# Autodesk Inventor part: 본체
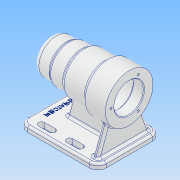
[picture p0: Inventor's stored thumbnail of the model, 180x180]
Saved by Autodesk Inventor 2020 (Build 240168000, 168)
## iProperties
Created: 2021-10
Part Number: 본체
Material: 알루미늄 6061
Document SubType Name: Modeling
Designer: user
Density: 2.7 g/cm^3
Appearance: 알루미늄 - 평지
Mass: 691.044 g
Surface Area: 699.056 cm^2
Volume: 255.942 cm^3
Author: user
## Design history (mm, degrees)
sketch "스케치1"
  geometry: L1 (56, 0)-(-56, 0); L2 (-56, 0)-(-56, 25); L3 (-56, 25)-(-32, 25); L4 (-32, 25)-(-32, 27); L5 (-32, 27)-(-10, 27); L6 (-10, 27)-(-10, 30); L7 (-10, 30)-(24, 30); L8 (24, 30)-(24, 34); L9 (24, 34)-(56, 34); L10 (56, 34)-(56, 0); 1 further point
  constraints: 20 end point, 7 perpendicular, 1 horizontal, 1 vertical
  dimensions: "d0" = 112 distance of L1.start L1.end; "d1" = 25 distance of L1.end L2.end; "d2" = 24 distance of L2.end L3.end; "d3" = 2 distance of L3.end L4.end; "d5" = 3 distance of L5.end L6.end; "d6" = 34 distance of L6.end L7.end; "d7" = 4 distance of L7.end L8.end; "d8" = 32 distance of L8.end L9.end; "d9" = 56 distance from line of point (0, 0) L2; "d10" = 34 distance from line of point (0, 0) L9; "d89" = 46 distance between parallel lines of L2 L6
revolve "회전1" sketch "스케치1" stored, may be unused: angle "d11" = 90 deg
node "작업 평면1"
sketch "스케치2"
  geometry: L1 (56, -45)-(-56, -45); L2 (-56, -45)-(-56, 45); L3 (-56, 45)-(56, 45); L4 (56, 45)-(56, -45); L5 (56, -45)-(-56, 45); L6 (-56, -45)-(56, 45); 1 further point
  constraints: 12 end point, 2 midpoint, 2 parallel, 1 horizontal, 1 perpendicular
  dimensions: "d13" = 112 distance of L1.start L1.end; "d14" = 90 distance of L1.end L2.end
extrude "돌출1" join sketch "스케치2" distance "d15" = 8; taper "d16" = 0 deg
sketch "스케치3"
  geometry: L1 (48, -4)-(-29, -4); L2 (-29, -4)-(-29, 4); L3 (-29, 4)-(48, 4); L4 (48, 4)-(48, -4); L5 (48, -4)-(-29, 4); L6 (-29, -4)-(48, 4); L7 (56, -45)-(56, 45) reference; 2 further points
  constraints: 12 end point, 2 midpoint, 2 parallel, 1 horizontal, 1 perpendicular
  dimensions: "d18" = 77 distance of L2.end L3.end; "d19" = 8 distance of L1.end L2.end; "d20" = 8 distance between parallel lines of L7 L4; "d21" = 4 distance from line of point (0, 0) L3
extrude "돌출2" join sketch "스케치3" stored distance "d22" = 8; taper "d23" = 0 deg
sketch "스케치4"
  geometry: L1 (-45, -62)-(45, -62) reference; L2 (-23.409, -24.658)-(-37, -62); L3 (23.409, -24.658)-(37, -62); L4 (-4, -62)-(-4, -33.764) reference; L5 (4, -62)-(4, -33.764) reference; L6 (-45, -70)-(-45, -62) reference; L7 (-45, -62)-(-4, -62) reference; L8 (-4, -62)-(-4, -33.764) reference; L9 (4, -33.764)-(4, -62) reference; L10 (4, -62)-(45, -62) reference; L11 (45, -62)-(45, -70) reference; L12 (45, -70)-(-45, -70) reference; L13 (-4, -62)-(4, -62) reference; A1 r 34 centre (0, 0) between (-23.409, -24.658) and (23.409, -24.658) reference; A2 r 34 centre (0, 0) between (4, -33.764) and (-4, -33.764) reference; A3 r 34 centre (0, 0) between (-4, -33.764) and (4, -33.764) reference
  constraints: 4 end point, 2 point on circle, 2 point on line
  dimensions: "d24" = 110 deg angle of L1 L2; "d25" = 8 distance of L2.end L1.start; "d26" = 110 deg angle of L1 L3; "d27" = 8 distance of L1.end L3.end
extrude "돌출3" join sketch "스케치4" distance "d28" = 8; taper "d29" = 0 deg
sketch "스케치5"
  geometry: C1 r 34 at (0, 0) reference; C2 r 21 at (0, 0)
  constraints: 1 centre point, 1 coincident
  dimensions: "d31" = 42 diameter of C2
feature "면 기울기1" dims angle "d30" = 15 deg
extrude "돌출4" cut sketch "스케치5" distance "d32" = 15; taper "d33" = 0 deg
sketch "스케치6"
  geometry: C1 r 21 at (0, 0) reference; C2 r 24 at (0, 0)
  constraints: 1 centre point, 1 coincident
  dimensions: "d34" = 48 diameter of C2
extrude "돌출5" cut sketch "스케치6" distance "d35" = 54; taper "d36" = 0 deg
sketch "스케치7"
  geometry: C1 r 24 at (0, 0) reference; C2 r 21 at (0, 0)
  constraints: 1 centre point, 1 coincident
  dimensions: "d37" = 42 diameter of C2
extrude "돌출6" cut sketch "스케치7" distance "d38" = 12; taper "d39" = 0 deg
sketch "스케치8"
  geometry: C1 r 21 at (0, 0) reference; C2 r 17.5 at (0, 0)
  constraints: 1 centre point, 1 coincident
  dimensions: "d40" = 35 diameter of C2
extrude "돌출7" cut sketch "스케치8" distance "d41" = 18; taper "d42" = 0 deg
sketch "스케치9"
  geometry: C1 r 17.5 at (0, 0) reference; C2 r 16 at (0, 0)
  constraints: 1 centre point, 1 coincident
  dimensions: "d43" = 32 diameter of C2
extrude "돌출8" cut sketch "스케치9" distance "d44" = 4; taper "d45" = 0 deg
sketch "스케치10"
  geometry: C1 r 16 at (0, 0) reference; C2 r 10.5 at (0, 0)
  constraints: 1 centre point, 1 coincident
  dimensions: "d46" = 21 diameter of C2
extrude "돌출9" cut sketch "스케치10" distance "d47" = 3; taper "d48" = 0 deg
sketch "스케치11" dims "d49" = 52
  geometry: C1 r 21 at (0, 0) reference; C2 r 34 at (0, 0) reference; 2 further points
  constraints: 2 horizontal alignment, 1 coincident, 2 other
hole "구멍1" sketch "스케치11" at (-26, 0) diameter "d50" = 3.242; stored, may be unused: countersink angle "d54" = 90 deg, drill point angle "d56" = 118 deg; dims "d51" = 8, "d52" = 4, "d53" = 2, "d55" = 11
sketch "스케치12"
  geometry: L1 (-56, 45)-(-56, -45) reference; L2 (56, 45)-(-56, 45) reference; L3 (40, -4)-(-29, -4) reference; L4 (-36, 33)-(-21, 33); L5 (-36, 28.5)-(-21, 28.5); L6 (-21, 37.5)-(-36, 37.5); L7 (4, 28.5)-(19, 28.5); L8 (4, 33)-(19, 33); L9 (19, 37.5)-(4, 37.5); A1 r 4.5 centre (-36, 33) between (-36, 37.5) and (-36, 28.5); A2 r 4.5 centre (-21, 33) between (-21, 28.5) and (-21, 37.5); A3 r 4.5 centre (19, 33) between (19, 28.5) and (19, 37.5); A4 r 4.5 centre (4, 33) between (4, 37.5) and (4, 28.5); 3 further points
  constraints: 16 end point, 8 point on circle, 8 tangent, 4 centre point, 3 parallel, 2 midpoint
  dimensions: "d60" = 15 distance of L4.start L4.end; "d61" = 20 distance from line of L1 L4.start; "d63" = 9 distance between parallel lines of L5 L6; "d64" = 33 vertical distance of point (0, 0) L4.start; "d65" = 15 distance of L8.start L8.end; "d66" = 9 distance between parallel lines of L7 L9; "d67" = 25 distance of L4.end L8.start; "d68" = 33 vertical distance of point (0, 0) L8.start; "d69" = 12 distance from line of L2 L8.end
extrude "돌출10" cut sketch "스케치12" extent not by distance; stored distance "d70" = 71.367; taper "d71" = 0 deg
fillet "모깎기1" dims "d72" = 12
fillet "모깎기2" dims "d73" = 3
fillet "모깎기3" dims "d74" = 3
fillet "모깎기4" dims "d75" = 3
fillet "모깎기5" dims "d76" = 8
chamfer "모따기1" distance "d78" = 1; stored, may be unused: second distance "d79" = 2, angle "d80" = 45 deg
sketch "스케치13"
  geometry: L1 (-56, 33)-(-56, -33) reference; 2 further points
  constraints: 1 horizontal alignment, 1 other
  dimensions: "d81" = 12 distance from line of L1 point (-44, 0)
fillet "모깎기7" dims "d82" = 3
fillet "모깎기8" dims "d83" = 3
fillet "모깎기9" dims "d84" = 3
feature "엠보싱1" dims "d0" = 112, "d1" = 25, "d2" = 24, "d3" = 2, "d5" = 3, "d6" = 34, "d7" = 4, "d8" = 32, "d9" = 56, "d10" = 34, "d85" = 0.5, "d86" = 0, "d89" = 46
fillet "모깎기10" dims "d87" = 0.3
fillet "모깎기11" dims "d88" = 3
node "솔리드1"
pattern_circular "원형 패턴1" dims angle "d58" = 360 deg
mirror "미러1"
node "절단 모서리 투영1"
feature "A9D066F2-1C7D-4E18-AEED-F7BC21143FA4" dims "d50" = 3.242, "d51" = 8, "d52" = 4, "d53" = 2, "d54" = 90 deg, "d55" = 11, "d56" = 118 deg
